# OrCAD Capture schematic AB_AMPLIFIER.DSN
size B
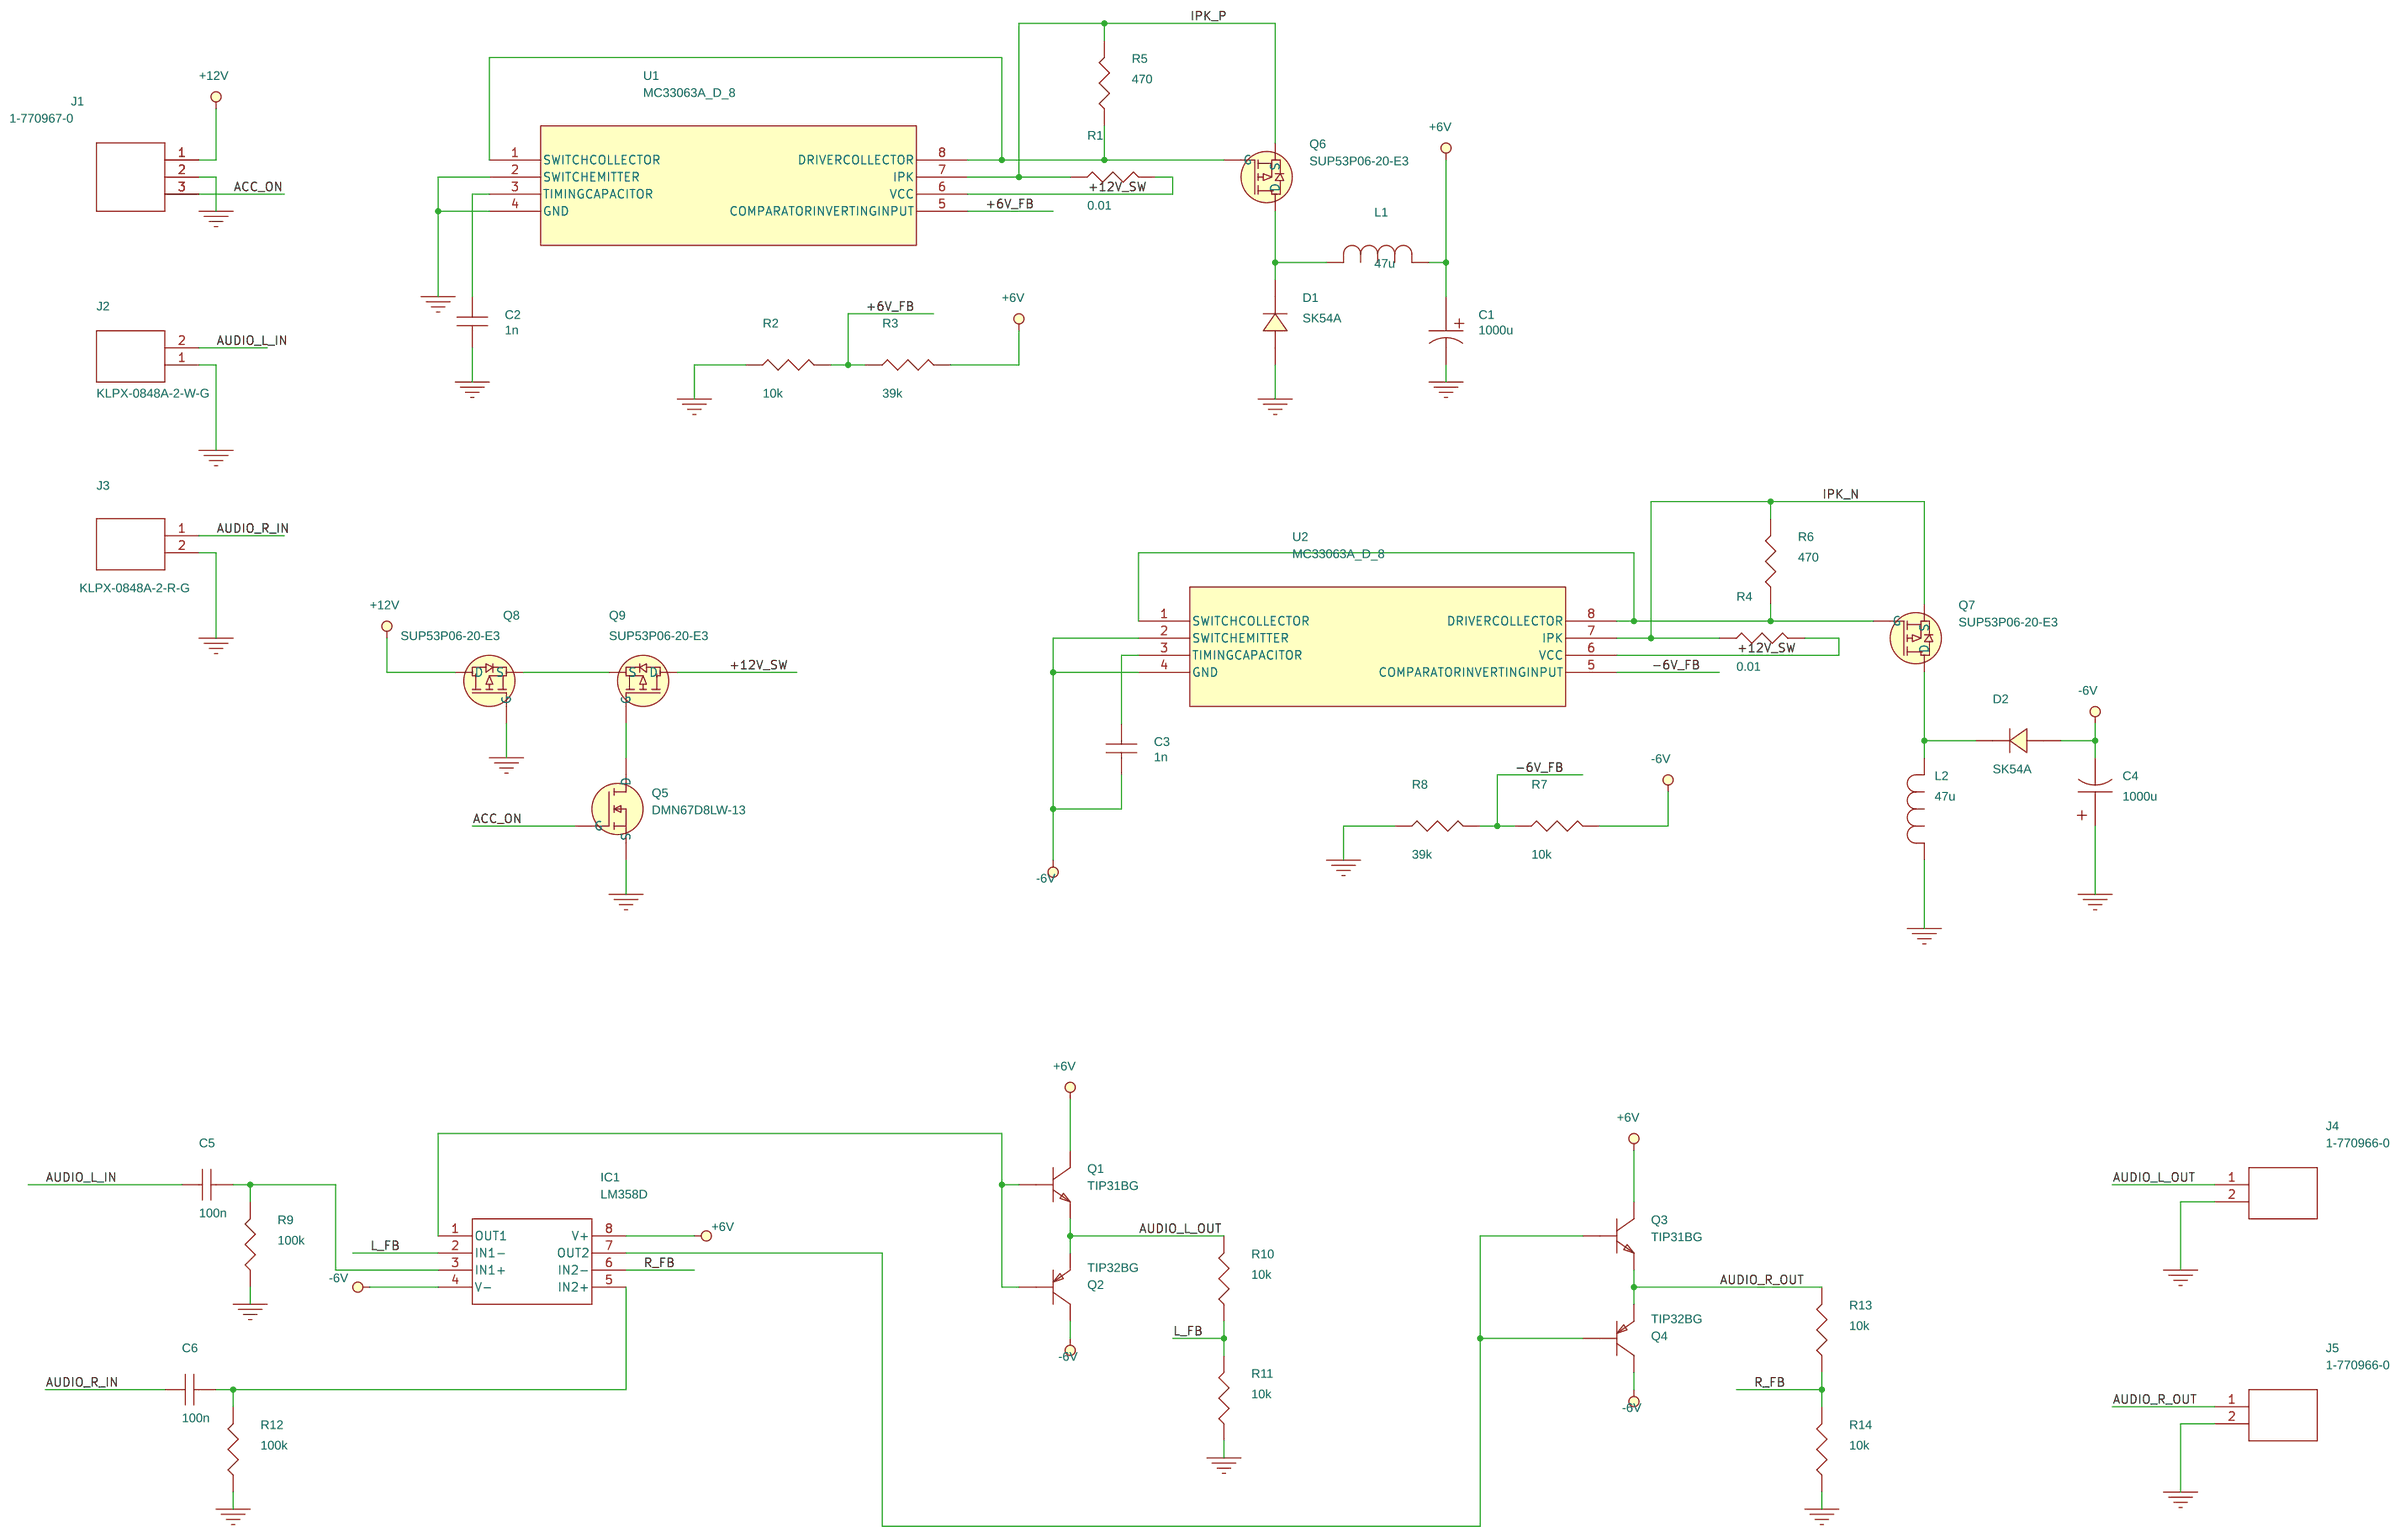
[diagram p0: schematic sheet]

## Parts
C1  1000u  [CAP_YX_16X25_RUB]
C2  1n  [SMC0603]
C3  1n  [SMC0603]
C4  1000u  [CAP_YX_16X25_RUB]
C5  100n  [SMC0603]
C6  100n  [SMC0603]
D1  SK54A  [SMD120612]
D2  SK54A  [SMD120612]
IC1  LM358D  [SOIC8]
J1  1-770967-0  [17709670]
J2  KLPX-0848A-2-W-G  [KLPX0848A2WG]
J3  KLPX-0848A-2-R-G  [KLPX0848A2RG]
J4  1-770966-0  [17709660]
J5  1-770966-0  [17709660]
L1  47u  [SML1210]
L2  47u  [SML1210]
Q1  TIP31BG  [TO-220AB_INF]
Q2  TIP32BG  [TO-220AB_INF]
Q3  TIP31BG  [TO-220AB_INF]
Q4  TIP32BG  [TO-220AB_INF]
Q5  DMN67D8LW-13  [SOT65P210X110-3N]
Q6  SUP53P06-20-E3  [TO_P06-20-E3_VIS]
Q7  SUP53P06-20-E3  [TO_P06-20-E3_VIS]
Q8  SUP53P06-20-E3  [TO_P06-20-E3_VIS]
Q9  SUP53P06-20-E3  [TO_P06-20-E3_VIS]
R1  0.01  [SMR1206]
R2  10k  [SMR0603]
R3  39k  [SMR0603]
R4  0.01  [SMR1206]
R5  470  [SMR0603]
R6  470  [SMR0603]
R7  10k  [SMR0603]
R8  39k  [SMR0603]
R9  100k  [SMR0603]
R10  10k  [SMR0603]
R11  10k  [SMR0603]
R12  100k  [SMR0603]
R13  10k  [SMR0603]
R14  10k  [SMR0603]
U1  MC33063A_D_8  [SOIC8]
U2  MC33063A_D_8  [SOIC8]

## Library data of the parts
C1 C4 = CAP_POL
C2 C3 C5 C6 = CAP_NP
D1 D2 = DIODE
IC1 = LM358D: Manufacturer Name: Texas Instruments; Source Id: SamacSys
J1 = 1-770967-0: Manufacturer Name: TE Connectivity; Source Id: SamacSys
J2 = KLPX-0848A-2-W-G: Manufacturer Name: Kycon; Source Id: SamacSys
J3 = KLPX-0848A-2-R-G: Manufacturer Name: Kycon; Source Id: SamacSys
J4 J5 = 1-770966-0: Manufacturer Name: TE Connectivity; Source Id: SamacSys
L1 L2 = 7447709470: Manufacturer Name: Wurth Electronics; Source Id: UL
Q1 Q3 = NPN_BCE
Q2 Q4 = PNP_BCE
Q5 = DMN67D8LW-13_0: Manufacturer Name: Diodes Incorporated; Source Id: SamacSys
Q6-Q9 = SUP53P06-20-E3_0: Manufacturer Name: Vishay; Source Id: UL
R1-R14 = RESISTOR
U1 U2 = MC33063ADR_0: Manufacturer Name: Texas Instruments; Manufacturer Part Number: MC33063ADR; Part Number: MC33063ADR; Source Id: UL

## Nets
+6V: C1.1 IC1.8(V+) L1.1 Q1.2(C) Q3.2(C) R3.2
+6V_FB: R2.2 R3.1 U1.5(COMPARATORINVERTINGINPUT)
+12V: J1.1 Q8.2(D)
+12V_SW: Q9.2(D) R1.2 R4.2 U1.6(VCC) U2.6(VCC)
-6V: C3.2 C4.2 D2.2(A) IC1.4(V-) Q2.2(C) Q4.2(C) R7.2 U2.2(SWITCHEMITTER) U2.4(GND)
-6V_FB: R7.1 R8.2 U2.5(COMPARATORINVERTINGINPUT)
GND: C1.2 C2.2 C4.1 D1.2(A) J1.2 J2.1 J3.2 J4.2 J5.2 L2.2 Q5.2(S) Q8.1(G) R2.1 R8.1 R9.1 R11.1 R12.1 R14.1 U1.2(SWITCHEMITTER) U1.4(GND)
ACC_ON: J1.3 Q5.1(G)
AUDIO_L_IN: C5.1 J2.2
AUDIO_L_OUT: J4.1 Q1.3(E) Q2.3(E) R10.2
AUDIO_R_IN: C6.1 J3.1
AUDIO_R_OUT: J5.1 Q3.3(E) Q4.3(E) R13.2
IPK_N: Q7.3(S) R4.1 R6.2 U2.7(IPK)
IPK_P: Q6.3(S) R1.1 R5.2 U1.7(IPK)
L_FB: IC1.2(IN1-) R10.1 R11.2
R_FB: IC1.6(IN2-) R13.1 R14.2
N01053: Q6.1(G) R5.1 U1.1(SWITCHCOLLECTOR) U1.8(DRIVERCOLLECTOR)
N01296: D1.1(K) L1.2 Q6.2(D)
N01586: C2.1 U1.3(TIMINGCAPACITOR)
N02316: D2.1(K) L2.1 Q7.2(D)
N02570: Q7.1(G) R6.1 U2.1(SWITCHCOLLECTOR) U2.8(DRIVERCOLLECTOR)
N02734: C3.1 U2.3(TIMINGCAPACITOR)
N04297: C5.2 IC1.3(IN1+) R9.2
N04399: IC1.1(OUT1) Q1.1(B) Q2.1(B)
N05881: C6.2 IC1.5(IN2+) R12.2
N06390: IC1.7(OUT2) Q3.1(B) Q4.1(B)
N06919: Q5.3(D) Q9.1(G)
N07129: Q8.3(S) Q9.3(S)
